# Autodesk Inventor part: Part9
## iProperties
Shininess: 77.0
Length Units: 11269
Angle Units: 11279
Time Units: 11290
Mass Units: 11283
Length Display Precision: 3
Angle Display Precision: 2
Created: 2002-01
Part Number: Part9
Document SubType Name: Modeling
Designer: ***
Density: 0.0
Volumn: 0.0
Area: 0.0
PropertySet Name: Model Information
Control State: 0
Master: False
Checked Out: False
Author: ***
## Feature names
1. Revolution1
